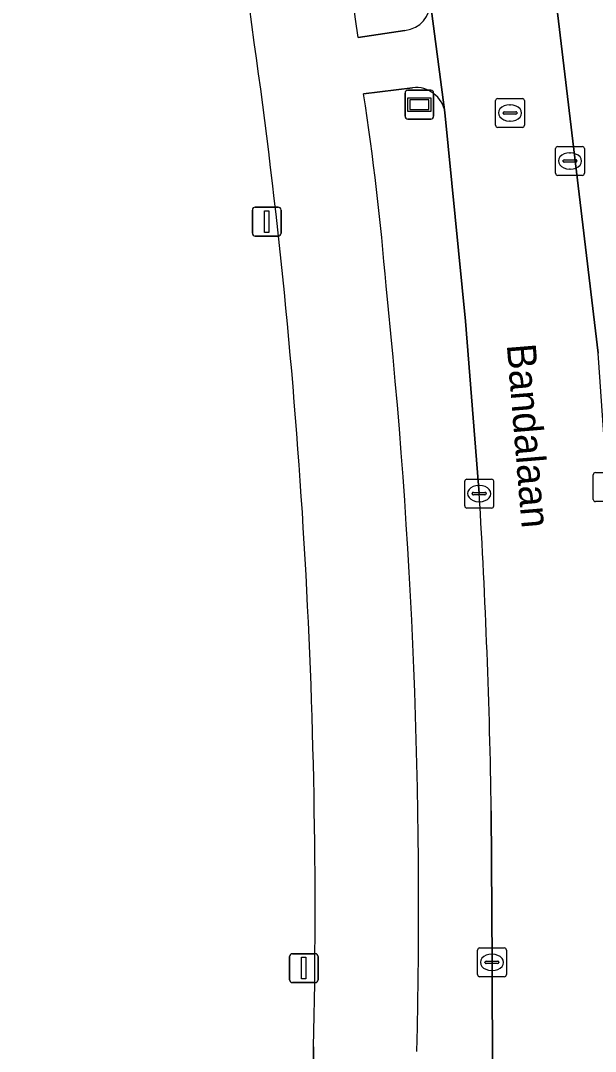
# Model space of a CAD drawing. Extents: x 162879 to 165540, y 384011 to 385181.
# Drawn here: x 163777.66 to 163797.54, y 384339.68 to 384375.35 of the extents above; entities that cross this region are included whole.
import ezdxf

# ---------------------------------------------------------------- set-up
doc = ezdxf.new("R2010")
doc.units = 0
for name, color, linetype in [('IMGEO_Fietspad_gesloten', 7, 'Continuous'), ('IMGEO_Groenvoorziening', 7, 'Continuous'), ('IMGEO_Kolk', 7, 'Continuous'), ('IMGEO_Lichtmast', 7, 'Continuous'), ('IMGEO_Openbare_ruimte_label', 7, 'Continuous'), ('IMGEO_Rijbaan_lokaal_open', 7, 'Continuous'), ('IMGEO_Rioolput', 7, 'Continuous'), ('IMGEO_Straatnaambord', 7, 'Continuous')]:
    doc.layers.add(name, color=color, linetype=linetype)

msp = doc.modelspace()

# ---------------------------------------------------------------- linework, layer by layer
at = {"layer": 'IMGEO_Fietspad_gesloten'}
for points in [[(163792.338, 384372.171), (163791.826, 384376.032)], [(163790.955, 384375.01), (163789.334, 384374.76)], [(163789.527, 384372.815), (163791.215, 384373.027)], [(163787.797, 384339.838), (163787.82, 384321.723)]]:
    msp.add_lwpolyline(points, dxfattribs=at)
for centre, radius, start, end in [((163578.641, 384347.699), 212.423, 7.31878, 18.44587), ((163573.957, 384346.303), 213.668, 7.60789, 18.44351), ((163790.862, 384375.972), 0.966, 275.5515, 3.5699), ((163572.064, 384344.537), 215.784, 358.75219, 8.00605), ((163694.154, 384358.347), 96.464, 4.65458, 8.62589), ((163791.326, 384372.009), 1.025, 9.1222, 96.2453), ((163586.511, 384344.707), 204.917, 358.59434, 6.01366)]:
    msp.add_arc(centre, radius, start, end, dxfattribs=at)
at = {"layer": 'IMGEO_Groenvoorziening'}
for points in [[(163789.334, 384374.76), (163790.955, 384375.01)], [(163791.215, 384373.027), (163789.527, 384372.815)], [(163793.524, 384358.981), (163793.045, 384364.945), (163792.338, 384372.171)], [(163794.044, 384316.879), (163794.029, 384323.01), (163793.966, 384342.761), (163793.942, 384348.009)], [(163787.82, 384321.723), (163787.797, 384339.838)]]:
    msp.add_lwpolyline(points, dxfattribs=at)
for centre, radius, start, end in [((163578.641, 384347.699), 212.423, 7.31878, 18.44587), ((163573.957, 384346.303), 213.668, 7.60789, 18.44351), ((163790.862, 384375.972), 0.966, 275.5515, 3.5699), ((163572.064, 384344.537), 215.784, 358.75219, 8.00605), ((163694.154, 384358.347), 96.464, 4.65458, 8.62589), ((163791.326, 384372.009), 1.025, 9.1222, 96.2453), ((163586.511, 384344.707), 204.917, 358.59434, 6.01366), ((163547.024, 384344.096), 246.949, 0.90788, 3.4556)]:
    msp.add_arc(centre, radius, start, end, dxfattribs=at)
at = {"layer": 'IMGEO_Kolk'}
for p, q in [((163797.466, 384358.781), (163797.466, 384359.633)), ((163797.541, 384359.707), (163798.393, 384359.707)), ((163793.022, 384358.555), (163793.022, 384359.407)), ((163793.097, 384359.481), (163793.949, 384359.481)), ((163793.51, 384359.261), (163793.535, 384359.261)), ((163794.023, 384359.407), (163794.023, 384358.555)), ((163793.281, 384358.975), (163793.281, 384358.987)), ((163793.719, 384358.938), (163793.321, 384358.938)), ((163793.324, 384359.024), (163793.722, 384359.024)), ((163793.765, 384358.987), (163793.765, 384358.975)), ((163793.533, 384358.701), (163793.508, 384358.701)), ((163798.393, 384358.707), (163797.541, 384358.707)), ((163793.949, 384358.481), (163793.097, 384358.481)), ((163793.539, 384343.261), (163794.391, 384343.261)), ((163793.464, 384342.335), (163793.464, 384343.187)), ((163793.952, 384343.041), (163793.977, 384343.041)), ((163794.465, 384343.187), (163794.465, 384342.335)), ((163793.723, 384342.755), (163793.723, 384342.767)), ((163794.161, 384342.718), (163793.763, 384342.718)), ((163793.766, 384342.804), (163794.164, 384342.804)), ((163794.207, 384342.767), (163794.207, 384342.755)), ((163794.391, 384342.261), (163793.539, 384342.261)), ((163793.975, 384342.481), (163793.95, 384342.481))]:
    msp.add_line(p, q, dxfattribs=at)
for points in [[(163797.466, 384358.781), (163797.466, 384359.633)], [(163797.541, 384359.707), (163798.393, 384359.707)], [(163793.022, 384358.555), (163793.022, 384359.407)], [(163793.097, 384359.481), (163793.949, 384359.481)], [(163794.023, 384359.407), (163794.023, 384358.555)], [(163798.393, 384358.707), (163797.541, 384358.707)], [(163793.949, 384358.481), (163793.097, 384358.481)], [(163793.539, 384343.261), (163794.391, 384343.261)], [(163793.464, 384342.335), (163793.464, 384343.187)], [(163794.465, 384343.187), (163794.465, 384342.335)], [(163794.391, 384342.261), (163793.539, 384342.261)]]:
    msp.add_lwpolyline(points, dxfattribs=at)
for centre, radius, start, end in [((163797.543, 384359.631), 0.0765, 91.552, 178.448), ((163797.543, 384359.631), 0.0765, 91.552, 178.448), ((163793.099, 384359.405), 0.0765, 91.552, 178.448), ((163793.099, 384359.405), 0.0765, 91.552, 178.448), ((163793.947, 384359.405), 0.0765, 1.552, 88.448), ((163793.947, 384359.405), 0.0765, 1.552, 88.448), ((163793.321, 384358.984), 0.0403, 85.8775, 175.7526), ((163793.318, 384358.974), 0.0366, 178.938, 274.7102), ((163793.722, 384358.981), 0.043, 264.8664, 352.4533), ((163793.726, 384358.986), 0.0386, 1.7309, 96.639), ((163793.099, 384358.557), 0.0765, 181.552, 268.448), ((163793.099, 384358.557), 0.0765, 181.552, 268.448), ((163793.947, 384358.557), 0.0765, 271.552, 358.448), ((163793.947, 384358.557), 0.0765, 271.552, 358.448), ((163797.543, 384358.783), 0.0765, 181.552, 268.448), ((163797.543, 384358.783), 0.0765, 181.552, 268.448), ((163793.541, 384343.185), 0.0765, 91.552, 178.448), ((163793.541, 384343.185), 0.0765, 91.552, 178.448), ((163794.389, 384343.185), 0.0765, 1.552, 88.448), ((163794.389, 384343.185), 0.0765, 1.552, 88.448), ((163793.763, 384342.764), 0.0403, 85.8775, 175.7526), ((163793.76, 384342.754), 0.0366, 178.938, 274.7102), ((163794.164, 384342.761), 0.043, 264.8664, 352.4533), ((163794.168, 384342.766), 0.0386, 1.7309, 96.639), ((163793.541, 384342.337), 0.0765, 181.552, 268.448), ((163793.541, 384342.337), 0.0765, 181.552, 268.448), ((163794.389, 384342.337), 0.0765, 271.552, 358.448), ((163794.389, 384342.337), 0.0765, 271.552, 358.448)]:
    msp.add_arc(centre, radius, start, end, dxfattribs=at)
for centre, major_axis, ratio, start_param, end_param in [((163793.509, 384358.981), (-0.387, 0.002), 0.722429, 4.712389, 7.853982), ((163793.534, 384358.981), (-0.39, 0.002), 0.717154, 1.570796, 4.712389), ((163793.951, 384342.761), (-0.387, 0.002), 0.722429, 4.712389, 7.853982), ((163793.976, 384342.761), (-0.39, 0.002), 0.717154, 1.570796, 4.712389)]:
    msp.add_ellipse(centre, major_axis=major_axis, ratio=ratio, start_param=start_param, end_param=end_param, dxfattribs=at)
at = {"layer": 'IMGEO_Lichtmast'}
for p, q in [((163785.78, 384368.895), (163786.57, 384368.895)), ((163786.57, 384368.895), (163785.78, 384368.895)), ((163785.68, 384367.995), (163785.68, 384368.795)), ((163785.68, 384368.795), (163785.68, 384367.995)), ((163786.67, 384368.795), (163786.67, 384367.995)), ((163786.67, 384367.995), (163786.67, 384368.795)), ((163786.57, 384367.895), (163785.78, 384367.895)), ((163785.78, 384367.895), (163786.57, 384367.895)), ((163786.962, 384342.16), (163786.962, 384342.96)), ((163786.962, 384342.96), (163786.962, 384342.16)), ((163787.062, 384343.06), (163787.852, 384343.06)), ((163787.852, 384343.06), (163787.062, 384343.06)), ((163787.952, 384342.96), (163787.952, 384342.16)), ((163787.952, 384342.16), (163787.952, 384342.96)), ((163787.852, 384342.06), (163787.062, 384342.06)), ((163787.062, 384342.06), (163787.852, 384342.06))]:
    msp.add_line(p, q, dxfattribs=at)
for points in [[(163786.1, 384368.77), (163786.25, 384368.77), (163786.25, 384368.02), (163786.1, 384368.02), (163786.1, 384368.77)], [(163787.382, 384342.935), (163787.532, 384342.935), (163787.532, 384342.185), (163787.382, 384342.185), (163787.382, 384342.935)]]:
    msp.add_lwpolyline(points, dxfattribs=at)
for centre, start, end in [((163785.78, 384368.795), 90, 180), ((163785.78, 384368.795), 90, 180), ((163786.57, 384368.795), 0, 90), ((163786.57, 384368.795), 360, 90), ((163785.78, 384367.995), 180, 270), ((163785.78, 384367.995), 180, 270), ((163786.57, 384367.995), 270, 0), ((163786.57, 384367.995), 270, 0), ((163787.062, 384342.96), 90, 180), ((163787.062, 384342.96), 90, 180), ((163787.852, 384342.96), 0, 90), ((163787.852, 384342.96), 360, 90), ((163787.062, 384342.16), 180, 270), ((163787.062, 384342.16), 180, 270), ((163787.852, 384342.16), 270, 0), ((163787.852, 384342.16), 270, 0)]:
    msp.add_arc(centre, 0.1, start, end, dxfattribs=at)
at = {"layer": 'IMGEO_Rijbaan_lokaal_open'}
for points in [[(163793.942, 384348.009), (163793.966, 384342.761), (163794.029, 384323.01), (163794.044, 384316.879), (163794.053, 384313.108), (163794.058, 384311.269), (163798.545, 384311.271), (163798.527, 384321.799), (163798.524, 384322.125), (163798.524, 384322.164), (163798.514, 384323.297), (163798.442, 384342.795), (163798.415, 384349.126), (163798.161, 384356.538), (163797.966, 384359.207), (163797.641, 384363.843), (163795.608, 384380.841), (163795.273, 384382.782), (163794.151, 384389.233), (163792.968, 384394.876), (163792.001, 384398.994), (163790.769, 384403.93)], [(163790.306, 384385.111), (163790.907, 384381.92), (163791.512, 384378.112), (163791.802, 384376.197), (163791.826, 384376.032), (163792.338, 384372.171), (163793.045, 384364.945), (163793.524, 384358.981)], [(163795.608, 384380.841), (163797.641, 384363.843)]]:
    msp.add_lwpolyline(points, dxfattribs=at)
msp.add_arc((163547.024, 384344.096), 246.949, 0.90788, 3.4556, dxfattribs=at)
at = {"layer": 'IMGEO_Rioolput'}
for p, q in [((163794.088, 384371.727), (163794.088, 384372.579)), ((163794.163, 384372.653), (163795.015, 384372.653)), ((163795.089, 384372.579), (163795.089, 384371.727)), ((163794.347, 384372.147), (163794.347, 384372.159)), ((163794.785, 384372.11), (163794.387, 384372.11)), ((163794.39, 384372.196), (163794.788, 384372.196)), ((163794.576, 384372.433), (163794.601, 384372.433)), ((163794.831, 384372.159), (163794.831, 384372.147)), ((163794.599, 384371.873), (163794.574, 384371.873)), ((163795.015, 384371.653), (163794.163, 384371.653)), ((163796.162, 384370.066), (163796.162, 384370.918)), ((163796.237, 384370.992), (163797.089, 384370.992)), ((163796.65, 384370.772), (163796.675, 384370.772)), ((163797.163, 384370.918), (163797.163, 384370.066)), ((163796.421, 384370.486), (163796.421, 384370.498)), ((163796.859, 384370.449), (163796.461, 384370.449)), ((163796.464, 384370.535), (163796.862, 384370.535)), ((163796.905, 384370.498), (163796.905, 384370.486)), ((163797.089, 384369.992), (163796.237, 384369.992)), ((163796.673, 384370.212), (163796.648, 384370.212))]:
    msp.add_line(p, q, dxfattribs=at)
for points in [[(163794.088, 384371.727), (163794.088, 384372.579)], [(163794.163, 384372.653), (163795.015, 384372.653)], [(163795.089, 384372.579), (163795.089, 384371.727)], [(163795.015, 384371.653), (163794.163, 384371.653)], [(163796.162, 384370.066), (163796.162, 384370.918)], [(163796.237, 384370.992), (163797.089, 384370.992)], [(163797.163, 384370.918), (163797.163, 384370.066)], [(163797.089, 384369.992), (163796.237, 384369.992)]]:
    msp.add_lwpolyline(points, dxfattribs=at)
for centre, radius, start, end in [((163794.165, 384372.577), 0.0765, 91.552, 178.448), ((163794.165, 384372.577), 0.0765, 91.552, 178.448), ((163795.013, 384372.577), 0.0765, 1.552, 88.448), ((163795.013, 384372.577), 0.0765, 1.552, 88.448), ((163794.387, 384372.156), 0.0403, 85.8775, 175.7526), ((163794.384, 384372.146), 0.0366, 178.938, 274.7102), ((163794.788, 384372.153), 0.043, 264.8664, 352.4533), ((163794.792, 384372.158), 0.0386, 1.7309, 96.639), ((163794.165, 384371.729), 0.0765, 181.552, 268.448), ((163794.165, 384371.729), 0.0765, 181.552, 268.448), ((163795.013, 384371.729), 0.0765, 271.552, 358.448), ((163795.013, 384371.729), 0.0765, 271.552, 358.448), ((163796.239, 384370.916), 0.0765, 91.552, 178.448), ((163796.239, 384370.916), 0.0765, 91.552, 178.448), ((163797.087, 384370.916), 0.0765, 1.552, 88.448), ((163797.087, 384370.916), 0.0765, 1.552, 88.448), ((163796.461, 384370.495), 0.0403, 85.8775, 175.7526), ((163796.458, 384370.485), 0.0366, 178.938, 274.7102), ((163796.862, 384370.492), 0.043, 264.8664, 352.4533), ((163796.866, 384370.497), 0.0386, 1.7309, 96.639), ((163796.239, 384370.068), 0.0765, 181.552, 268.448), ((163796.239, 384370.068), 0.0765, 181.552, 268.448), ((163797.087, 384370.068), 0.0765, 271.552, 358.448), ((163797.087, 384370.068), 0.0765, 271.552, 358.448)]:
    msp.add_arc(centre, radius, start, end, dxfattribs=at)
for centre, major_axis, ratio, start_param, end_param in [((163794.575, 384372.153), (-0.387, 0.002), 0.722429, 4.712389, 7.853982), ((163794.6, 384372.153), (-0.39, 0.002), 0.717154, 1.570796, 4.712389), ((163796.649, 384370.492), (-0.387, 0.002), 0.722429, 4.712389, 7.853982), ((163796.674, 384370.492), (-0.39, 0.002), 0.717154, 1.570796, 4.712389)]:
    msp.add_ellipse(centre, major_axis=major_axis, ratio=ratio, start_param=start_param, end_param=end_param, dxfattribs=at)
at = {"layer": 'IMGEO_Straatnaambord'}
for p, q in [((163790.957, 384372.041), (163790.957, 384372.841)), ((163790.957, 384372.841), (163790.957, 384372.041)), ((163791.057, 384372.941), (163791.847, 384372.941)), ((163791.847, 384372.941), (163791.057, 384372.941)), ((163791.947, 384372.841), (163791.947, 384372.041)), ((163791.947, 384372.041), (163791.947, 384372.841)), ((163791.847, 384371.941), (163791.057, 384371.941)), ((163791.057, 384371.941), (163791.847, 384371.941))]:
    msp.add_line(p, q, dxfattribs=at)
for points in [[(163791.058, 384372.673), (163791.846, 384372.673), (163791.846, 384372.209), (163791.058, 384372.209), (163791.058, 384372.673)], [(163791.123, 384372.608), (163791.123, 384372.274), (163791.781, 384372.274), (163791.781, 384372.608), (163791.123, 384372.608)]]:
    msp.add_lwpolyline(points, dxfattribs=at)
for centre, start, end in [((163791.057, 384372.841), 90, 180), ((163791.057, 384372.841), 90, 180), ((163791.847, 384372.841), 0, 90), ((163791.847, 384372.841), 360, 90), ((163791.057, 384372.041), 180, 270), ((163791.057, 384372.041), 180, 270), ((163791.847, 384372.041), 270, 0), ((163791.847, 384372.041), 270, 0)]:
    msp.add_arc(centre, 0.1, start, end, dxfattribs=at)

# ---------------------------------------------------------------- texts
at = {"layer": 'IMGEO_Openbare_ruimte_label'}
msp.add_text('Bandalaan', height=1, rotation=274.7018, dxfattribs=at).set_placement((163794.475, 384364.133))

doc.saveas('drawing.dxf')
